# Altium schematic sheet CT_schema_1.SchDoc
size 381 x 329 mm
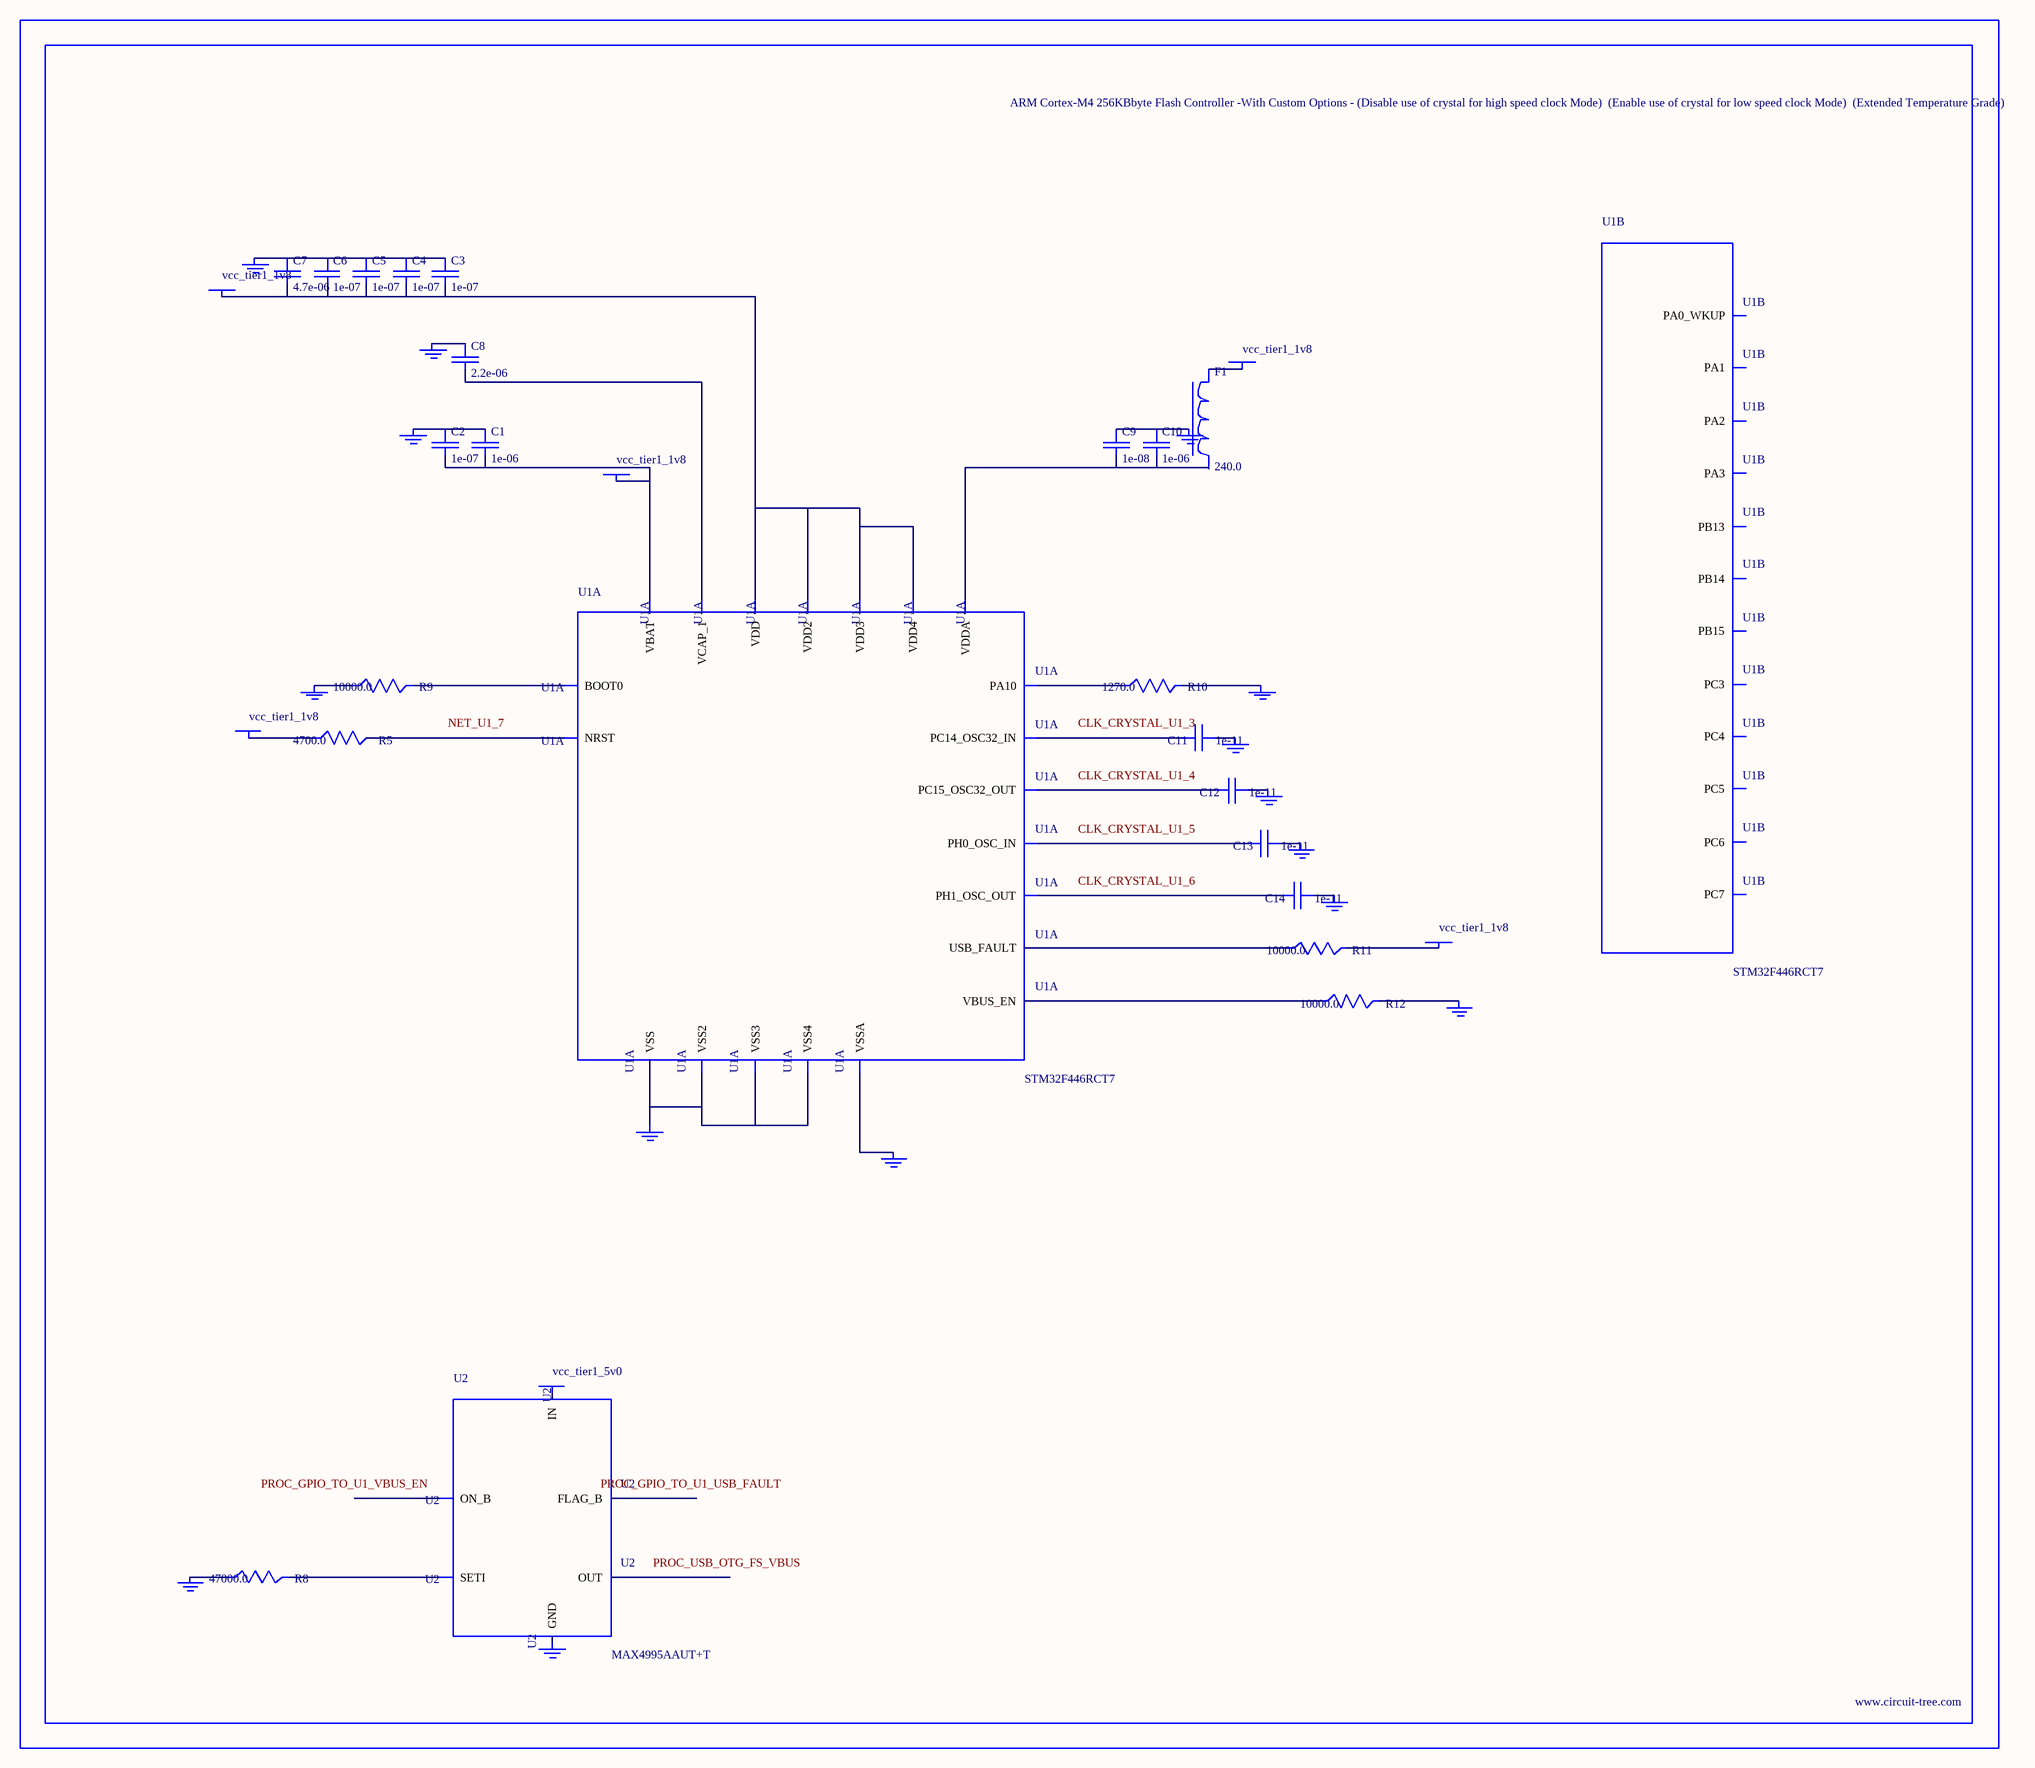
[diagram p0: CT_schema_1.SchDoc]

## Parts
BORDER0  (no value)
C1  1e-06  [C0603]
C2  1e-07  [C0603]
C3  1e-07  [C0603]
C4  1e-07  [C0603]
C5  1e-07  [C0603]
C6  1e-07  [C0603]
C7  4.7e-06  [C0603]
C8  2.2e-06  [C0603]
C9  1e-08  [C0603]
C10  1e-06  [C0603]
C11  1e-11  [C0402]
C12  1e-11  [C0402]
C13  1e-11  [C0402]
C14  1e-11  [C0402]
F1  240.0  [L0603]
GND_INSTANCE_0_0  (no value)
GND_INSTANCE_0_1  (no value)
GND_INSTANCE_0_2  (no value)
GND_INSTANCE_0_3  (no value)
GND_INSTANCE_0_4  (no value)
GND_INSTANCE_0_5  (no value)
GND_INSTANCE_0_6  (no value)
GND_INSTANCE_0_7  (no value)
GND_INSTANCE_0_8  (no value)
GND_INSTANCE_0_9  (no value)
GND_INSTANCE_0_10  (no value)
GND_INSTANCE_0_11  (no value)
GND_INSTANCE_0_12  (no value)
GND_INSTANCE_0_13  (no value)
GND_INSTANCE_0_14  (no value)
POWER_INSTANCE_0_0  vcc_tier1_1v8
POWER_INSTANCE_0_1  vcc_tier1_1v8
POWER_INSTANCE_0_2  vcc_tier1_1v8
POWER_INSTANCE_0_3  vcc_tier1_1v8
POWER_INSTANCE_0_4  vcc_tier1_1v8
POWER_INSTANCE_0_5  vcc_tier1_5v0
R5  4700.0  [R0603]
R8  47000.0  [R0603]
R9  10000.0  [R0603]
R10  1270.0  [R0603]
R11  10000.0  [R0603]
R12  10000.0  [R0603]
U1  STM32F446RCT7  [LQFP64]  (parts A,B of 7)
U2  MAX4995AAUT+T  [SOT-23-6]

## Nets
NetC1_1: C1.1 C2.1 GND_INSTANCE_0_0.0(GND)
NetC1_2: C1.2 C2.2 POWER_INSTANCE_0_0.0(PWR) U1.1(VBAT)
NetC3_1: C3.1 C4.1 C5.1 C6.1 C7.1 GND_INSTANCE_0_8.0(GND)
NetC3_2: C3.2 C4.2 C5.2 C6.2 C7.2 POWER_INSTANCE_0_3.0(PWR) U1.19(VDD) U1.32(VDD2) U1.48(VDD3) U1.64(VDD4)
NetC8_1: C8.1 GND_INSTANCE_0_9.0(GND)
NetC8_2: C8.2 U1.30(VCAP_1)
NetC9_1: C9.1 C10.1 GND_INSTANCE_0_7.0(GND)
NetC9_2: C9.2 C10.2 U1.13(VDDA)
NetC11_1: C11.1 GND_INSTANCE_0_2.0(GND)
NetC11_2: C11.2 U1.3(PC14_OSC32_IN)
NetC12_1: C12.1 GND_INSTANCE_0_3.0(GND)
NetC12_2: C12.2 U1.4(PC15_OSC32_OUT)
NetC13_1: C13.1 GND_INSTANCE_0_4.0(GND)
NetC13_2: C13.2 U1.5(PH0_OSC_IN)
NetC14_1: C14.1 GND_INSTANCE_0_5.0(GND)
NetC14_2: C14.2 U1.6(PH1_OSC_OUT)
NetF1_1: F1.1 POWER_INSTANCE_0_2.0(PWR)
NetGND_INSTANCE_0_1_0: GND_INSTANCE_0_1.0(GND) R12.2
NetGND_INSTANCE_0_6_0: GND_INSTANCE_0_6.0(GND) U1.12(VSSA)
NetGND_INSTANCE_0_10_0: GND_INSTANCE_0_10.0(GND) R10.2
NetGND_INSTANCE_0_11_0: GND_INSTANCE_0_11.0(GND) R9.1
NetGND_INSTANCE_0_12_0: GND_INSTANCE_0_12.0(GND) U1.18(VSS) U1.31(VSS2) U1.47(VSS3) U1.63(VSS4)
NetGND_INSTANCE_0_13_0: GND_INSTANCE_0_13.0(GND) R8.1
NetPOWER_INSTANCE_0_1_0: POWER_INSTANCE_0_1.0(PWR) R11.2
NetPOWER_INSTANCE_0_4_0: POWER_INSTANCE_0_4.0(PWR) R5.1
NetR5_2: R5.2 U1.7(NRST)
NetR8_2: R8.2 U2.3(SETI)
NetR9_2: R9.2 U1.60(BOOT0)
NetR10_1: R10.1 U1.43(PA10)
NetR11_1: R11.1 U1.8(USB_FAULT)
NetR12_1: R12.1 U1.2(VBUS_EN)

Not connected (* = marked no-connect by the designer): F1 2; GND_INSTANCE_0_14 0(GND); POWER_INSTANCE_0_5 0(PWR); U1 11(PC3) 14(PA0_WKUP) 15(PA1) 16(PA2) 17(PA3) 24(PC4) 25(PC5) 34(PB13) 35(PB14) 36(PB15) 37(PC6) 38(PC7); U2 1(OUT) 2(GND) 4(ON_B) 5(IN) 6(FLAG_B)

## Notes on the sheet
- Labels drawn without touching a wire or pin: CLK_CRYSTAL_U1_3, CLK_CRYSTAL_U1_4, CLK_CRYSTAL_U1_5, CLK_CRYSTAL_U1_6, NET_U1_7, PROC_GPIO_TO_U1_USB_FAULT, PROC_GPIO_TO_U1_VBUS_EN, PROC_USB_OTG_FS_VBUS

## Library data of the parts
BORDER0 = BORDER_PAGE0
C1 C10 = C0603C105K3RACTU
C2-C6 = 06035C104K4Z2A
C7 = GRM188R6YA475KE15D
C8 = C0603C225K8RACTU
C9 = 06035C103K4Z2A
C11-C14 = C0402C100K3GACTU
F1 = Z0603C241ASMST
GND_INSTANCE_0_0-GND_INSTANCE_0_14 = GND
POWER_INSTANCE_0_0-POWER_INSTANCE_0_5 = PWR
R5 = RC0603JR-074K7L
R8 = RC0603JR-0747KL
R9 R11 R12 = RC0603JR-0710KL
R10 = RC0603FR-071K27L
